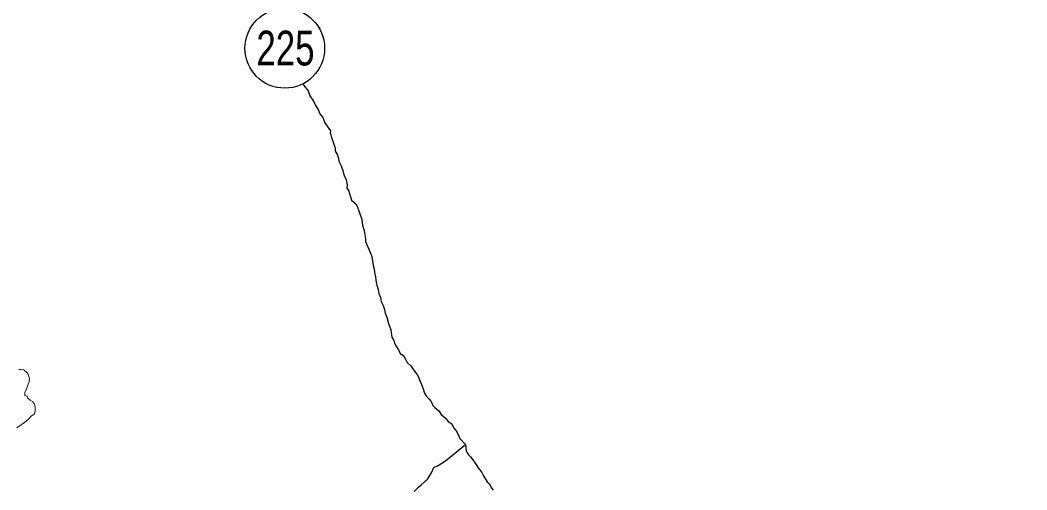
# Model space of a CAD drawing. Extents: x -1643653 to 4543381, y 1624270 to 13878484.
# Drawn here: x 589726 to 591755, y 8907871 to 8908816 of the extents above; entities that cross this region are included whole.
import ezdxf
from ezdxf.enums import TextEntityAlignment as Align

# ---------------------------------------------------------------- set-up
doc = ezdxf.new("R2010")
doc.units = 0
doc.header["$LTSCALE"] = 200
doc.layers.add('6', color=7, linetype='Continuous', lineweight=13)
doc.layers.add('60', color=7, linetype='Continuous', lineweight=13)

msp = doc.modelspace()

# ---------------------------------------------------------------- linework, layer by layer
at = {"layer": '6', "lineweight": 25}
for points in [[(590296.3, 8908687.9), (590297.6, 8908684.8), (590306, 8908674.3), (590309.9, 8908664.2), (590316.8, 8908653.2), (590320.8, 8908644.6), (590326.7, 8908636.1), (590329.6, 8908628), (590336.1, 8908620), (590340, 8908609.4), (590347.9, 8908598.4), (590351.4, 8908593.3), (590350.9, 8908589.3), (590352.3, 8908585.3), (590353.3, 8908579.8), (590356.7, 8908570.8), (590358.7, 8908564.8), (590360.6, 8908558.7), (590360.6, 8908552.7), (590364.5, 8908546.2), (590367.5, 8908538.7), (590368.4, 8908532.7), (590371.9, 8908524.1), (590375.3, 8908515.6), (590378.7, 8908503.5), (590382.7, 8908494.5), (590384.6, 8908484.5), (590384.5, 8908479), (590388, 8908471.9), (590393.8, 8908453.9)], [(590393.8, 8908453.9), (590402.3, 8908446.3), (590404.8, 8908441.8), (590406.2, 8908437.8), (590408.7, 8908432.7), (590410.2, 8908426.7), (590411.6, 8908422.7), (590414.6, 8908415.2), (590415.5, 8908403.7), (590418.9, 8908392.6), (590420.3, 8908384.1), (590421.8, 8908376.1), (590421.7, 8908370.6), (590425.7, 8908361.5), (590428.6, 8908355.5), (590434.5, 8908340.4)], [(590434.5, 8908340.4), (590436.4, 8908326.4), (590437.8, 8908319.4), (590439.3, 8908314.9), (590440.3, 8908308.4), (590441.7, 8908299.3), (590443.1, 8908288.3), (590444.6, 8908282.8), (590447.5, 8908274.3), (590448.9, 8908266.2), (590452.4, 8908257.7), (590453.3, 8908249.7), (590457.3, 8908241.7), (590460.2, 8908234.1), (590461.6, 8908226.1), (590464.6, 8908218.6), (590468, 8908205.5), (590472.9, 8908193)], [(590472.9, 8908193), (590474.8, 8908177.9), (590478.7, 8908171.4), (590480.2, 8908165.9), (590484.1, 8908158.9), (590488.6, 8908152.8), (590492, 8908145.3), (590498.5, 8908141.2), (590502.5, 8908133.7), (590505.9, 8908127.2), (590513.4, 8908120.6), (590517.3, 8908114.1), (590520.3, 8908109.6), (590527.2, 8908101), (590530.7, 8908092), (590534.6, 8908082.9), (590538, 8908074.4), (590541, 8908065.3), (590544.4, 8908060.3), (590550.4, 8908053.3), (590554.3, 8908048.7), (590557.8, 8908040.7), (590561.7, 8908036.2), (590569.7, 8908029.6), (590574.7, 8908022.6), (590582.1, 8908015.5), (590588.5, 8908008.5), (590596, 8908003.9), (590600, 8907994.9), (590604.4, 8907989.8), (590608.3, 8907982.3), (590611.8, 8907973.8), (590623.7, 8907962.2)], [(590547.1, 8907892.1), (590554.7, 8907905), (590559.8, 8907915.5), (590568.4, 8907919.5), (590582.9, 8907929.4), (590623.7, 8907962.2)], [(590623.7, 8907962.2), (590624.6, 8907949.1), (590627.1, 8907945.1), (590629.6, 8907941.1), (590633.5, 8907937.1), (590638.5, 8907931), (590642.9, 8907924.5), (590645.4, 8907920.5), (590648.9, 8907914.9), (590652.3, 8907910.9), (590656.3, 8907905.4), (590659.7, 8907898.8), (590663.7, 8907892.3), (590667.2, 8907886.8), (590672.1, 8907882.7), (590675.1, 8907875.7), (590679.5, 8907870.2)], [(590519.9, 8907867.7), (590528.5, 8907876.2), (590534.1, 8907881.1), (590547.1, 8907892.1)]]:
    msp.add_lwpolyline(points, dxfattribs=at)
at = {"layer": '6'}
for points in [[(589741.4, 8908105.2), (589733.5, 8908112.2), (589727, 8908113.3), (589723, 8908113.3)], [(589719.1, 8907995.7), (589727.6, 8908001.6), (589734.2, 8908006.1), (589741.7, 8908012.6), (589748.2, 8908019), (589754.8, 8908023.5), (589755.8, 8908030), (589755.9, 8908036.5), (589755.4, 8908040.5), (589754, 8908044.5), (589750.5, 8908048.6), (589746, 8908051.6), (589741.5, 8908055.1), (589739.6, 8908059.1), (589735.1, 8908060.7), (589735.1, 8908066.7), (589738.7, 8908074.2), (589741.2, 8908081.2), (589743.8, 8908088.7), (589744.3, 8908094.7), (589741.4, 8908105.2)]]:
    msp.add_lwpolyline(points, dxfattribs=at)
at = {"layer": '6', "lineweight": 25}
msp.add_circle((590259.2, 8908759.7), 80.3, dxfattribs=at)
at = {"layer": '60', "lineweight": 25}
msp.add_spline([(814781, 9009175.5), (814787.2, 9009173.4), (814796.9, 9009173.4), (814799.4, 9009172.4), (814805.1, 9009174.5), (814805.6, 9009176.5), (814811.7, 9009179.5), (814811.7, 9009179.5), (814801.5, 9009181), (814790.7, 9009181.5), (814784.1, 9009183.1), (814777.4, 9009185.1), (814778.4, 9009175.5)], degree=3, dxfattribs=at)

# ---------------------------------------------------------------- texts
at = {"layer": '6', "width": 0.75}
msp.add_text('225', height=70, dxfattribs=at).set_placement((590260.5, 8908725.1), align=Align.CENTER)

doc.saveas('drawing.dxf')
